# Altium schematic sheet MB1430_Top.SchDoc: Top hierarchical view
size A4; Date: Not used; ApprovedBy: Not used; CheckedBy: Not used; Author: Not used; CompanyName: STMicroelectronics; DrawnBy: Not used; Engineer: Not used; Organization: Not used; Address1: Not used; Address2: Not used; Address3: Not used; Address4: Not used; DocumentNumber: Not used; Revision: A-01-P3; SheetNumber: 2; SheetTotal: 7
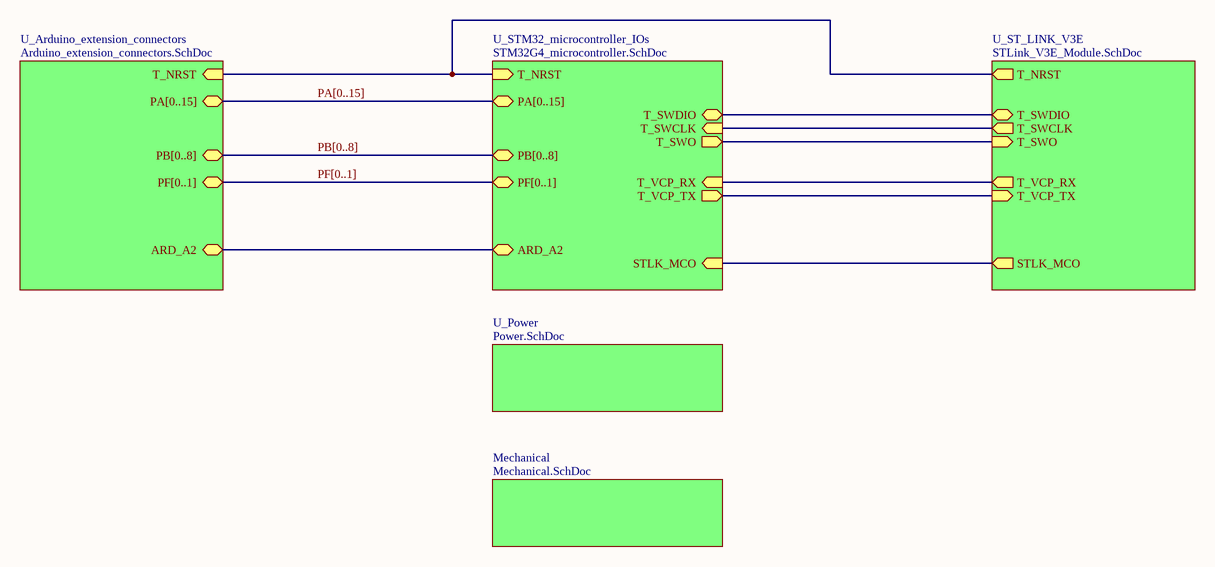
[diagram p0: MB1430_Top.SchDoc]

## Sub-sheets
Mechanical = Mechanical.SchDoc: no entries
U_Arduino_extension_connectors = Arduino_extension_connectors.SchDoc: PA[0..15] (bidir), PF[0..1] (bidir), T_NRST, PB[0..8] (bidir), ARD_A2
U_Power = Power.SchDoc: no entries
U_ST_LINK_V3E = STLink_V3E_Module.SchDoc: T_SWCLK, T_SWO, T_NRST, STLK_MCO, T_SWDIO, T_VCP_TX, T_VCP_RX
U_STM32_microcontroller_IOs = STM32G4_microcontroller.SchDoc: PA[0..15] (bidir), PF[0..1] (bidir), STLK_MCO, T_NRST, T_VCP_TX, T_VCP_RX, T_SWCLK, T_SWO, T_SWDIO, PB[0..8] (bidir), ARD_A2

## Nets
(unnamed): sheet U_Arduino_extension_connectors/T_NRST, sheet U_STM32_microcontroller_IOs/T_NRST, sheet U_ST_LINK_V3E/T_NRST
(unnamed): sheet U_Arduino_extension_connectors/ARD_A2, sheet U_STM32_microcontroller_IOs/ARD_A2  [a separate net that carries the same name]
(unnamed): sheet U_STM32_microcontroller_IOs/STLK_MCO, sheet U_ST_LINK_V3E/STLK_MCO  [a separate net that carries the same name]
(unnamed): sheet U_STM32_microcontroller_IOs/T_VCP_TX, sheet U_ST_LINK_V3E/T_VCP_TX  [a separate net that carries the same name]
(unnamed): sheet U_STM32_microcontroller_IOs/T_VCP_RX, sheet U_ST_LINK_V3E/T_VCP_RX  [a separate net that carries the same name]
(unnamed): sheet U_STM32_microcontroller_IOs/T_SWCLK, sheet U_ST_LINK_V3E/T_SWCLK  [a separate net that carries the same name]
(unnamed): sheet U_STM32_microcontroller_IOs/T_SWO, sheet U_ST_LINK_V3E/T_SWO  [a separate net that carries the same name]
(unnamed): sheet U_STM32_microcontroller_IOs/T_SWDIO, sheet U_ST_LINK_V3E/T_SWDIO  [a separate net that carries the same name]

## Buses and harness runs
bus PA[0..15] = sheet U_Arduino_extension_connectors/PA[0..15] = sheet U_STM32_microcontroller_IOs/PA[0..15]
bus PB[0..8] = sheet U_Arduino_extension_connectors/PB[0..8] = sheet U_STM32_microcontroller_IOs/PB[0..8]
bus PF[0..1] = sheet U_Arduino_extension_connectors/PF[0..1] = sheet U_STM32_microcontroller_IOs/PF[0..1]

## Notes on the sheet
- Cuttable part on PCB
